(* Logix 5000 project; controller logix5561 vendor 1 type 14 code 54 rev 19.11; software revision 19.01 *)

TASK MainTask (continuous, watchdog 500 ms) : MainProgram

MODULES
   Local : vendor 1 type 14 code 54 (ICP 0, rev 19.11)
      EIP : 1756-ENBT (ICP 1, Ethernet 192.168.16.199, rev 6.1)
         Mitsubishi_Inverter : ETHERNET-MODULE (Ethernet 192.168.16.22, rev 1.1, Output RPI 10 ms)   // Conveyor #6 first roller
END_MODULES

ADD_ON_INSTRUCTION FRA7NWIE_ACDC_Drive_Profile   (* revision 1.0 *)
// Interface for AC/DC Drive Profile that uses Input Assembly Instance 71 and Output Assembly Instance 21.
VAR_IN_OUT
   I_Data : INT[2]; {required}   // Input data
   O_Data : INT[2]; {required}   // Output data
END_VAR
VAR_INPUT
   RunForward : BOOL; {required}   // Run forward
   RunReverse : BOOL; {required}   // Run reverse
   ResetFault : BOOL; {required}   // Reset fault
   NetControl : BOOL; {required}   // Control from network
   NetReference : BOOL; {required}   // Speed reference from network
   SpeedReference : INT; {access Read Only, required}   // Speed reference (RPM)
END_VAR
VAR_OUTPUT
   Faulted : BOOL; {access Read Only, visible}   // Faulted
   RunningForward : BOOL; {access Read Only, visible}   // Running forward
   RunningReverse : BOOL; {access Read Only, visible}   // Running reverse
   Ready : BOOL; {access Read Only, visible}   // Ready
END_VAR
VAR_INPUT
   ControlFromNet : BOOL; {visible}   // Controlled from network
   ReferenceFromNet : BOOL; {visible}   // Speed referenced from network
END_VAR
VAR_OUTPUT
   AtReference : BOOL; {access Read Only, visible}   // Up-to-speed
   DriveState : SINT; {access Read Only, visible}   // Drive state (0 = vendor specific, 1 = startup, 2 = not ready, 3 = ready, 4 = enabled, 5 = stopping, 6 = fault stop, 7 = faulted)
   SpeedActual : INT; {access Read Only, visible}   // Actual speed (RPM)
END_VAR
VAR
   temp : INT; {access None}
END_VAR

ROUTINE Logic   (* ladder *)
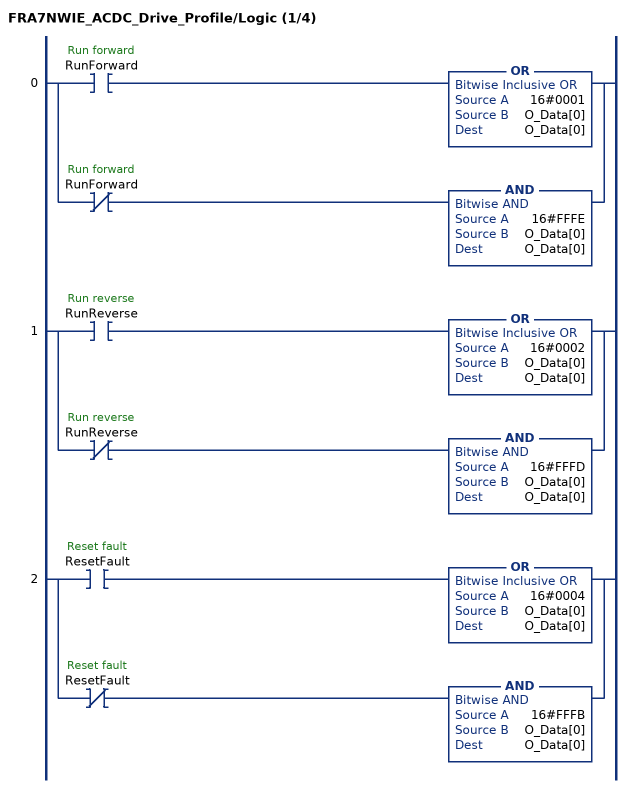
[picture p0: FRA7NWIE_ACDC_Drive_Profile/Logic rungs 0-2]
   0: [XIC(RunForward) OR(16#0001,O_Data[0],O_Data[0]) ,XIO(RunForward) AND(16#FFFE,O_Data[0],O_Data[0]) ];
   1: [XIC(RunReverse) OR(16#0002,O_Data[0],O_Data[0]) ,XIO(RunReverse) AND(16#FFFD,O_Data[0],O_Data[0]) ];
   2: [XIC(ResetFault) OR(16#0004,O_Data[0],O_Data[0]) ,XIO(ResetFault) AND(16#FFFB,O_Data[0],O_Data[0]) ];
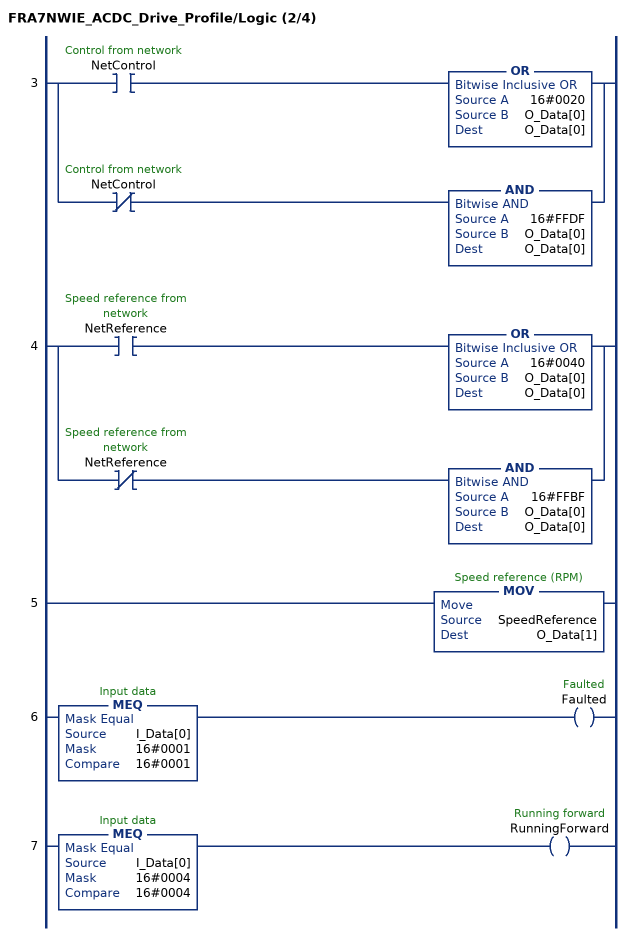
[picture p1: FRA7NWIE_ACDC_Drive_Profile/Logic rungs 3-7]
   3: [XIC(NetControl) OR(16#0020,O_Data[0],O_Data[0]) ,XIO(NetControl) AND(16#FFDF,O_Data[0],O_Data[0]) ];
   4: [XIC(NetReference) OR(16#0040,O_Data[0],O_Data[0]) ,XIO(NetReference) AND(16#FFBF,O_Data[0],O_Data[0]) ];
   5: MOV(SpeedReference,O_Data[1]);
   6: MEQ(I_Data[0],16#0001,16#0001)OTE(Faulted);
   7: MEQ(I_Data[0],16#0004,16#0004)OTE(RunningForward);
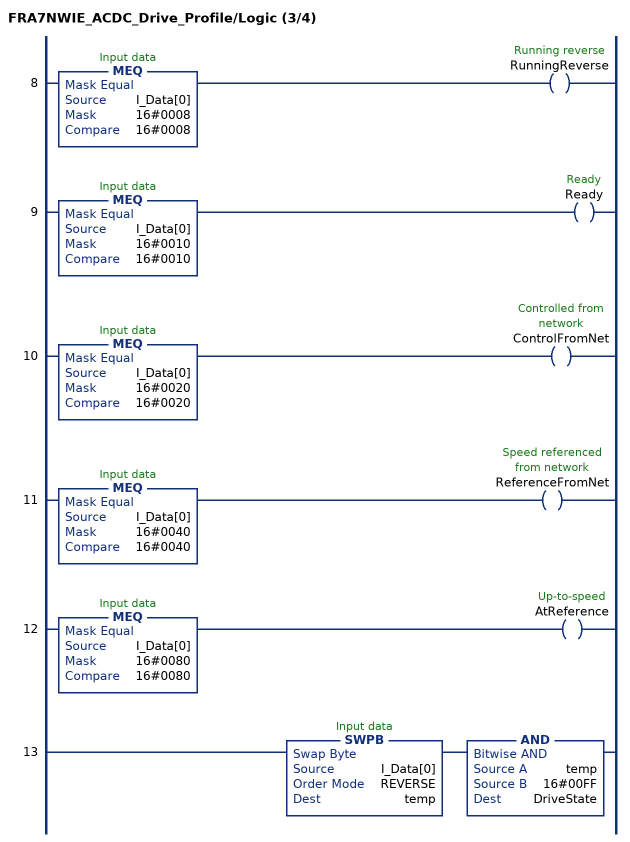
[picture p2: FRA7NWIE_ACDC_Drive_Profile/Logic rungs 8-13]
   8: MEQ(I_Data[0],16#0008,16#0008)OTE(RunningReverse);
   9: MEQ(I_Data[0],16#0010,16#0010)OTE(Ready);
   10: MEQ(I_Data[0],16#0020,16#0020)OTE(ControlFromNet);
   11: MEQ(I_Data[0],16#0040,16#0040)OTE(ReferenceFromNet);
   12: MEQ(I_Data[0],16#0080,16#0080)OTE(AtReference);
   13: SWPB(I_Data[0],REVERSE,temp)AND(temp,16#00FF,DriveState);
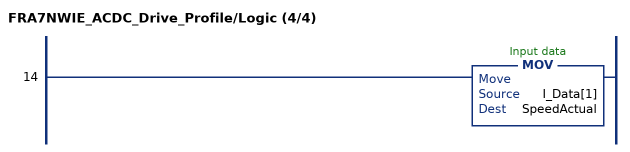
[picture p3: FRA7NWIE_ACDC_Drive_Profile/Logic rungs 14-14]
   14: MOV(I_Data[1],SpeedActual);
END_ROUTINE
END_ADD_ON_INSTRUCTION

VAR_GLOBAL   (* controller tags *)
   acdc_aoi : FRA7NWIE_ACDC_Drive_Profile;
   net_ctrl : BOOL;   // Control from network
   net_ref : BOOL;   // Speed reference from network
   reset : BOOL;   // Fault reset
   run_fwd : BOOL;   // Run forward direction
   run_rev : BOOL;   // Run reverse direction
   speed_ref : INT := 1370;   // Speed reference (RPM)
END_VAR

PROGRAM MainProgram   (* main routine MainRoutine *)

ROUTINE MainRoutine   (* ladder *)
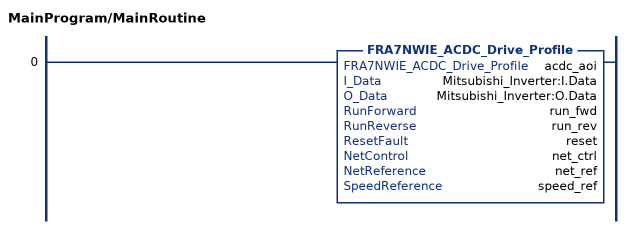
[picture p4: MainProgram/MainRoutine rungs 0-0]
   0: FRA7NWIE_ACDC_Drive_Profile(acdc_aoi,Mitsubishi_Inverter:I.Data,Mitsubishi_Inverter:O.Data,run_fwd,run_rev,reset,net_ctrl,net_ref,speed_ref);
END_ROUTINE
END_PROGRAM
